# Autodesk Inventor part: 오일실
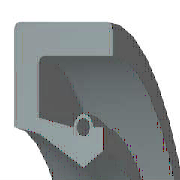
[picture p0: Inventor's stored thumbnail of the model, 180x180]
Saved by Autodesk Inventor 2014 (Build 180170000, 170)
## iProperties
IsCustomPart: 1
Created: 2015-12
Part Number: 오일실
Material: 일반
Description: 오일-실
Document SubType Name: Modeling
Standard: KS B 2804
Designer: mdu
Standards Organization: KS
Language: ko-KR
Size Designation: S - 15 30 7
Categories: <MemberInstance><Categories><Category DisplayName="샤프트 부품" InternalName="7f7aeb1f-a693-4053-b835-cee3144e0d98" Mnemonic="SHFT"><Category DisplayName="실링" Intern
Density: 1 g/cm^3
Appearance: 기본값
Author: mdu
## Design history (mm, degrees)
revolve "본체" stored, may be unused: angle "d17" = 90 deg
revolve "스프링1" stored, may be unused: angle "d18" = 90 deg
body "Solid1"
sketch "스케치1"
  geometry: L1 (0, 15)-(7, 15); L2 (7, 15)-(7, 13.75); L3 (7, 13.75)-(1.75, 13.75); L4 (0, 15)-(0, 9.6); L5 (0, 9.6)-(1.75, 9.25); L6 (1.75, 9.25)-(4.9, 7.5); L7 (4.9, 7.5)-(0, 7.5); L8 (6.3, 8.375)-(6.3, 9.6); L9 (0, 0)-(9.586, 0) reference; L10 (4.9, 7.5)-(6.3, 8.375); L11 (0, 18)-(0, -3) reference; L12 (-1.917, 0)-(11.503, 0) reference; L13 (4.2, 9.6)-(1.75, 10.09); L14 (1.75, 10.09)-(1.75, 13.75); L15 (6.3, 9.6)-(5.6, 9.6); C1 r 0.455 at (4.9, 9.6); A1 r 0.7 centre (4.9, 9.6) between (5.6, 9.6) and (4.2, 9.6)
  constraints: 26 end point, 5 horizontal alignment, 4 perpendicular, 2 centre point, 2 collinear, 2 horizontal, 2 parallel, 2 point on circle, 2 point on line, 2 vertical alignment, 1 coincident
  dimensions: "d0" = 30 diameter of L1 L9 (= SD2); "d1" = 16.75 diameter of L8.start L9 (= ABDM); "d2" = 1.25 distance of L1.end L2.end (computed from SD); "d3" = 0.91 diameter of C1 (= SPDI); "d4" = 1.4 diameter of A1 (= SPDA); "d5" = 15 diameter of L6.end L9 (= NND); "d6" = 18.5 diameter of L5.end L9 (= TKDM); "d7" = 19.2 diameter of L4.end L9 (= HLDM); "d8" = 4.9 distance from line of C1.centre L4 (= SPDST); "d9" = 6.3 distance between parallel lines of L8 L4 (= SDI); "d10" = 7 distance between parallel lines of L2 L4 (= SWDT); "d12" = 1.75 distance between parallel lines of L14 L4 (= SD)
fillet "모깎기1" dims "d11" = 0.3 (= RR)
other parameters: "SD2" = 30 [user parameter; used in 1 equation term], "SWDT" = 7 [user parameter; used in 1 equation term], "RR" = 0.3 [user parameter; used in 1 equation term], "SD" = 1.75 [user parameter; used in 2 equation terms], "NND" = 15 [user parameter; used in 1 equation term], "SPDA" = 1.4 [user parameter; used in 1 equation term], "SPDI" = 0.91 [user parameter; used in 1 equation term], "TKDM" = 18.5 [user parameter; used in 1 equation term], "HLDM" = 19.2 [user parameter; used in 1 equation term], "ABDM" = 16.75 [user parameter; used in 1 equation term], "SDI" = 6.3 [user parameter; used in 1 equation term], "SPDST" = 4.9 [user parameter; used in 1 equation term], "d13" = 0, "d14" = 0, "d15" = 0, "LAB" = 0.35 [user parameter]
